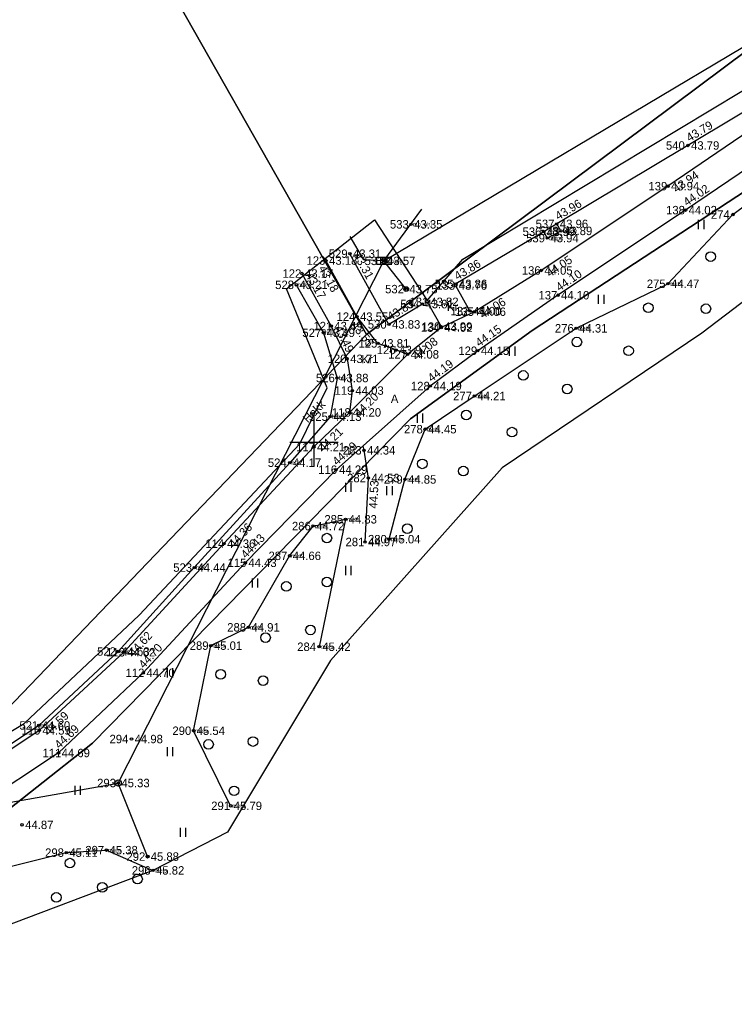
# Model space of a CAD drawing. Extents: x 505800 to 507326, y 6540058 to 6542128.
# Drawn here: x 506275.6 to 506334.8, y 6540254 to 6540335 of the extents above; entities that cross this region are included whole.
import ezdxf

# ---------------------------------------------------------------- set-up
doc = ezdxf.new("R2010")
doc.units = 0
for name, color, linetype in [('AED', 7, 'Continuous'), ('ELRAJATISMP', 7, 'Continuous'), ('HALJASTUS', 7, 'Continuous'), ('KORGUS-EH2000', 7, 'Continuous'), ('MAAMUDEL', 7, 'Continuous'), ('MOOTKORG-EH2000', 7, 'Continuous'), ('MOOTMPUNKT', 7, 'Continuous'), ('MOOTNR', 7, 'Continuous'), ('MOOTPIIR', 7, 'Continuous'), ('MPKAABEL', 7, 'Continuous'), ('MPOHULIIN', 7, 'Continuous'), ('PIIR', 7, 'Continuous'), ('POST', 7, 'Continuous'), ('TEE', 7, 'Continuous'), ('VORK', 7, 'Continuous')]:
    doc.layers.add(name, color=color, linetype=linetype)

msp = doc.modelspace()

# ---------------------------------------------------------------- linework, layer by layer
at = {"layer": 'AED'}
msp.add_line((506319.036, 6540317.461), (506311.755, 6540313.133), dxfattribs=at)
for points in [[(506338.82, 6540329.309), (506330.987, 6540324.61), (506320.117, 6540318.11)], [(506308.981, 6540311.464), (506306.211, 6540309.773), (506302.975, 6540315.637)]]:
    msp.add_lwpolyline(points, dxfattribs=at)
at = {"layer": 'ELRAJATISMP'}
for p, q in [((506305.667, 6540315.342), (506305.667, 6540314.745)), ((506305.938, 6540315.342), (506305.938, 6540314.745))]:
    msp.add_line(p, q, dxfattribs=at)
msp.add_lwpolyline([(506305.205, 6540315.342), (506306.4, 6540315.342), (506306.4, 6540314.745), (506305.205, 6540314.745)], close=True, dxfattribs=at)
at = {"layer": 'HALJASTUS'}
for p, q in [((506331.841, 6540318.44), (506331.841, 6540317.679)), ((506332.296, 6540318.44), (506332.296, 6540317.679)), ((506323.554, 6540312.231), (506323.554, 6540311.47)), ((506324.009, 6540312.231), (506324.009, 6540311.47)), ((506316.187, 6540307.944), (506316.187, 6540307.183)), ((506316.642, 6540307.944), (506316.642, 6540307.183)), ((506308.54, 6540302.376), (506308.54, 6540301.615)), ((506308.995, 6540302.376), (506308.995, 6540301.615)), ((506302.614, 6540296.647), (506302.614, 6540295.886)), ((506303.069, 6540296.647), (506303.069, 6540295.886)), ((506306.017, 6540296.367), (506306.017, 6540295.606)), ((506306.473, 6540296.367), (506306.473, 6540295.606)), ((506302.614, 6540289.757), (506302.614, 6540288.996)), ((506303.069, 6540289.757), (506303.069, 6540288.996)), ((506294.877, 6540288.715), (506294.877, 6540287.954)), ((506295.332, 6540288.715), (506295.332, 6540287.954)), ((506287.831, 6540281.264), (506287.831, 6540280.503)), ((506288.286, 6540281.264), (506288.286, 6540280.503)), ((506287.831, 6540274.734), (506287.831, 6540273.973)), ((506288.286, 6540274.734), (506288.286, 6540273.973)), ((506280.184, 6540271.529), (506280.184, 6540270.768)), ((506280.639, 6540271.529), (506280.639, 6540270.768)), ((506288.912, 6540268.044), (506288.912, 6540267.283)), ((506289.367, 6540268.044), (506289.367, 6540267.283))]:
    msp.add_line(p, q, dxfattribs=at)
for points in [[(506306.227, 6540291.97), (506307.537, 6540296.92), (506309.208, 6540301.088), (506313.28, 6540303.838), (506321.716, 6540309.454), (506329.329, 6540313.144), (506334.711, 6540318.885), (506344.435, 6540326.129), (506351.88, 6540331.712), (506354.071, 6540331.501), (506356.847, 6540327.167), (506360.247, 6540322.568)], [(506298.533, 6540313.056), (506300.788, 6540309.079), (506301.915, 6540305.332), (506301.34, 6540302.125), (506297.996, 6540298.309), (506290.085, 6540289.615), (506283.777, 6540282.658), (506277.199, 6540276.527), (506270.683, 6540272.177), (506261.206, 6540268.283), (506249.615, 6540264.383), (506241.896, 6540261.54), (506240.872, 6540264.129), (506242.157, 6540264.661)], [(506293.096, 6540269.863), (506290.021, 6540276.088), (506291.453, 6540283.145), (506294.563, 6540284.663), (506297.982, 6540290.588), (506299.925, 6540293.056), (506302.613, 6540293.618), (506300.432, 6540283.052)], [(506248.469, 6540250.071), (506251.633, 6540258.04), (506254.539, 6540261.644), (506261.335, 6540263.775), (506263.852, 6540262.439), (506271.144, 6540263.911), (506279.471, 6540265.984), (506282.803, 6540266.189), (506286.653, 6540264.508)]]:
    msp.add_lwpolyline(points, dxfattribs=at)
for centre in [(506332.876, 6540315.4), (506327.711, 6540311.154), (506332.476, 6540311.074), (506321.786, 6540308.309), (506326.07, 6540307.588), (506317.342, 6540305.545), (506320.985, 6540304.424), (506312.617, 6540302.26), (506316.404, 6540300.845), (506308.974, 6540298.214), (506312.377, 6540297.613), (506307.733, 6540292.846), (506301.071, 6540292.058), (506297.708, 6540288.052), (506301.071, 6540288.417), (506299.71, 6540284.447), (506295.987, 6540283.806), (506292.263, 6540280.761), (506295.787, 6540280.24), (506291.262, 6540274.952), (506294.946, 6540275.193), (506293.384, 6540271.106), (506279.775, 6540265.111), (506285.38, 6540263.789), (506282.457, 6540263.108), (506278.654, 6540262.267)]:
    msp.add_circle(centre, 0.4, dxfattribs=at)
at = {"layer": 'KORGUS-EH2000'}
for centre in [(506330.987, 6540324.61), (506329.323, 6540321.237), (506330.786, 6540319.25), (506334.711, 6540318.885), (506308.044, 6540318.072), (506320.117, 6540318.11), (506319.036, 6540317.461), (506320.459, 6540317.528), (506319.332, 6540316.931), (506302.975, 6540315.637), (506300.992, 6540315.071), (506305.802, 6540315.044), (506299, 6540313.993), (506318.831, 6540314.247), (506298.533, 6540313.056), (506311.755, 6540313.133), (506329.329, 6540313.144), (506307.646, 6540312.702), (506311.742, 6540313), (506308.981, 6540311.464), (506309.38, 6540311.646), (506320.213, 6540312.197), (506312.927, 6540310.878), (506313.303, 6540310.828), (506303.553, 6540310.418), (506300.788, 6540309.079), (506301.425, 6540309.637), (506306.211, 6540309.773), (506310.53, 6540309.596), (506310.542, 6540309.512), (506321.716, 6540309.454), (506305.297, 6540308.204), (506306.809, 6540307.659), (506313.574, 6540307.593), (506302.746, 6540306.922), (506307.759, 6540307.29), (506301.915, 6540305.332), (506303.175, 6540304.292), (506309.643, 6540304.666), (506313.28, 6540303.838), (506301.34, 6540302.125), (506302.957, 6540302.479), (506309.208, 6540301.088), (506299.99, 6540299.616), (506304.139, 6540299.338), (506297.996, 6540298.309), (506301.827, 6540297.731), (506304.496, 6540297.04), (506307.537, 6540296.92), (506302.613, 6540293.618), (506299.925, 6540293.056), (506306.227, 6540291.97), (506292.541, 6540291.599), (506304.224, 6540291.74), (506297.982, 6540290.588), (506290.085, 6540289.615), (506294.306, 6540290.01), (506294.563, 6540284.663), (506291.453, 6540283.145), (506300.432, 6540283.052), (506283.777, 6540282.658), (506284.251, 6540282.595), (506285.858, 6540280.887), (506277.199, 6540276.527), (506277.243, 6540276.116), (506290.021, 6540276.088), (506284.88, 6540275.4), (506278.831, 6540274.243), (506283.784, 6540271.755), (506293.096, 6540269.863), (506275.813, 6540268.286), (506282.803, 6540266.189), (506279.471, 6540265.984), (506286.211, 6540265.655), (506286.653, 6540264.508)]:
    msp.add_circle(centre, 0.1, dxfattribs=at)
at = {"layer": 'MOOTMPUNKT'}
for centre in [(506330.987, 6540324.61), (506329.323, 6540321.237), (506330.786, 6540319.25), (506334.711, 6540318.885), (506308.044, 6540318.072), (506320.117, 6540318.11), (506319.036, 6540317.461), (506320.459, 6540317.528), (506319.332, 6540316.931), (506302.975, 6540315.637), (506300.992, 6540315.071), (506305.802, 6540315.044), (506299, 6540313.993), (506318.831, 6540314.247), (506298.533, 6540313.056), (506311.755, 6540313.133), (506329.329, 6540313.144), (506307.646, 6540312.702), (506311.742, 6540313), (506308.981, 6540311.464), (506309.38, 6540311.646), (506320.213, 6540312.197), (506312.927, 6540310.878), (506313.303, 6540310.828), (506303.553, 6540310.418), (506300.788, 6540309.079), (506301.425, 6540309.637), (506306.211, 6540309.773), (506310.53, 6540309.596), (506310.542, 6540309.512), (506321.716, 6540309.454), (506305.297, 6540308.204), (506306.809, 6540307.659), (506313.574, 6540307.593), (506302.746, 6540306.922), (506307.759, 6540307.29), (506301.915, 6540305.332), (506303.175, 6540304.292), (506309.643, 6540304.666), (506313.28, 6540303.838), (506301.34, 6540302.125), (506302.957, 6540302.479), (506309.208, 6540301.088), (506299.99, 6540299.616), (506304.139, 6540299.338), (506297.996, 6540298.309), (506301.827, 6540297.731), (506304.496, 6540297.04), (506307.537, 6540296.92), (506302.613, 6540293.618), (506299.925, 6540293.056), (506306.227, 6540291.97), (506292.541, 6540291.599), (506304.224, 6540291.74), (506297.982, 6540290.588), (506290.085, 6540289.615), (506294.306, 6540290.01), (506294.563, 6540284.663), (506291.453, 6540283.145), (506300.432, 6540283.052), (506283.777, 6540282.658), (506284.251, 6540282.595), (506285.858, 6540280.887), (506277.199, 6540276.527), (506277.243, 6540276.116), (506290.021, 6540276.088), (506284.88, 6540275.4), (506278.831, 6540274.243), (506283.784, 6540271.755), (506293.096, 6540269.863), (506275.813, 6540268.286), (506282.803, 6540266.189), (506279.471, 6540265.984), (506286.211, 6540265.655), (506286.653, 6540264.508)]:
    msp.add_circle(centre, 0.1, dxfattribs=at)
at = {"layer": 'MOOTPIIR'}
for points in [[(506240.253, 6540270.959), (506245.955, 6540263.864), (506266.133, 6540270.794), (506275.983, 6540276.683), (506285.511, 6540285.657), (506298.843, 6540299.878), (506301.086, 6540304.525), (506297.722, 6540312.738), (506305.023, 6540318.445), (506309.38, 6540311.746), (506312.325, 6540315.185), (506338.029, 6540330.648), (506336.908, 6540340.183), (506347.357, 6540347.554), (506370.89, 6540361.705), (506382.389, 6540366.462), (506390.076, 6540368.866), (506400.572, 6540374.13), (506410.565, 6540381.71), (506441.143, 6540393.151), (506453.59, 6540403.335), (506461.402, 6540393.473), (506495.448, 6540402.285)], [(506495.183, 6540386.603), (506455.807, 6540378.751), (506413.936, 6540356.957), (506411.426, 6540354.112), (506402.307, 6540351.523), (506391.999, 6540341.498), (506380.901, 6540334.942), (506360.247, 6540322.568), (506353.013, 6540324.95), (506332.133, 6540309.036), (506315.598, 6540297.889), (506301.375, 6540281.904), (506292.827, 6540267.673), (506286.653, 6540264.508), (506248.469, 6540250.071)]]:
    msp.add_lwpolyline(points, dxfattribs=at)
at = {"layer": 'MPKAABEL'}
msp.add_lwpolyline([(506305.802, 6540315.044), (506304.129, 6540315.129), (506302.991, 6540317.073)], dxfattribs=at)
at = {"layer": 'MPOHULIIN'}
for q in [(506338.064, 6540334.279), (506308.946, 6540319.316)]:
    msp.add_line((506305.802, 6540315.044), q, dxfattribs=at)
msp.add_lwpolyline([(506112.189, 6540233.927), (506153.828, 6540249.522), (506196.936, 6540256.778), (506240.207, 6540264.027), (506283.784, 6540271.755), (506305.802, 6540315.044)], dxfattribs=at)
at = {"layer": 'PIIR'}
for points in [[(506215.95, 6540254.34), (506268.55, 6540273.9), (506274.54, 6540277.85), (506304.35, 6540308.95), (506340.34, 6540335.82), (506458.7, 6540391.28), (506563.96, 6540420.02)], [(506497.85, 6540391.32), (506462.8, 6540384.69), (506453.27, 6540382.76), (506413.82, 6540364.84), (506374.55, 6540342.6), (506353.59, 6540332.53), (506318.07, 6540309.28), (506308, 6540301.95), (506281.65, 6540275.05), (506272.39, 6540267.75), (506224.13, 6540249.92)], [(506224.13, 6540249.92), (506272.39, 6540267.75), (506281.65, 6540275.05), (506308, 6540301.95), (506318.07, 6540309.28), (506353.59, 6540332.53), (506374.55, 6540342.6), (506413.82, 6540364.84), (506453.27, 6540382.76), (506462.8, 6540384.69), (506495.14, 6540337.45), (506342.85, 6540237.27), (506260.72, 6540195.9), (506215.68, 6540179.69)]]:
    msp.add_lwpolyline(points, dxfattribs=at)
for points in [[(506281.36, 6540349.61), (506321.08, 6540373.36), (506324.04, 6540375.18), (506326.14, 6540370.11), (506340.34, 6540335.82), (506304.35, 6540308.95), (506282.62, 6540347.28)], [(506190.15, 6540321.81), (506202.45, 6540325.81), (506206.43, 6540327.67), (506257.9, 6540343.01), (506275.56, 6540347.96), (506281.36, 6540349.61), (506282.62, 6540347.28), (506304.35, 6540308.95), (506274.54, 6540277.85), (506268.55, 6540273.9), (506215.95, 6540254.34)]]:
    msp.add_lwpolyline(points, close=True, dxfattribs=at)
at = {"layer": 'POST'}
for points in [[(506307.646, 6540312.702), (506305.802, 6540315.044)], [(506286.211, 6540265.655), (506283.784, 6540271.755)]]:
    msp.add_lwpolyline(points, dxfattribs=at)
for centre, radius in [((506305.802, 6540315.044), 0.25), ((506307.646, 6540312.702), 0.2), ((506283.784, 6540271.755), 0.25), ((506286.211, 6540265.655), 0.125), ((506286.211, 6540265.655), 0.105), ((506286.211, 6540265.655), 0.0851), ((506286.211, 6540265.655), 0.0651), ((506286.211, 6540265.655), 0.0451), ((506286.211, 6540265.655), 0.0251), ((506286.211, 6540265.655), 0.00511)]:
    msp.add_circle(centre, radius, dxfattribs=at)
at = {"layer": 'TEE'}
for points in [[(506340.898, 6540329.111), (506329.323, 6540321.237), (506318.831, 6540314.247), (506313.303, 6540310.828), (506310.542, 6540309.512), (506307.759, 6540307.29), (506302.957, 6540302.479), (506299.99, 6540299.616), (506292.541, 6540291.599), (506284.251, 6540282.595), (506277.243, 6540276.116), (506270.928, 6540271.917), (506261.747, 6540268.058), (506250.031, 6540264.042), (506237.432, 6540259.066)], [(506342.338, 6540327.065), (506330.786, 6540319.25), (506320.213, 6540312.197), (506313.574, 6540307.593), (506309.643, 6540304.666), (506301.827, 6540297.731), (506294.306, 6540290.01), (506285.858, 6540280.887), (506278.831, 6540274.243), (506272.138, 6540269.835), (506262.639, 6540265.724), (506250.904, 6540261.782), (506238.366, 6540256.809)], [(506319.036, 6540317.461), (506319.332, 6540316.931), (506320.459, 6540317.528), (506320.117, 6540318.11)], [(506320.117, 6540318.11), (506319.036, 6540317.461)], [(506307.759, 6540307.29), (506306.809, 6540307.659), (506305.297, 6540308.204), (506303.553, 6540310.418), (506300.992, 6540315.071)], [(506299, 6540313.993), (506301.425, 6540309.637), (506302.746, 6540306.922), (506303.175, 6540304.292), (506302.957, 6540302.479)], [(506311.742, 6540313), (506312.927, 6540310.878), (506313.303, 6540310.828)], [(506309.38, 6540311.646), (506310.53, 6540309.596), (506310.542, 6540309.512)], [(506304.059, 6540299.711), (506304.139, 6540299.338), (506304.496, 6540297.04), (506304.224, 6540291.74)]]:
    msp.add_lwpolyline(points, dxfattribs=at)
at = {"layer": 'VORK'}
for p, q in [((506300, 6540302), (506300, 6540298)), ((506298, 6540300), (506302, 6540300))]:
    msp.add_line(p, q, dxfattribs=at)

# ---------------------------------------------------------------- texts
at = {"layer": 'HALJASTUS'}
msp.add_text('Hekk', height=0.7, rotation=44.60512, dxfattribs=at).set_placement((506299.489, 6540301.567))
at = {"layer": 'KORGUS-EH2000'}
for s, rotation, p in [(' 43.79', 30.95913, (506330.897, 6540324.76)), (' 43.94', 34.22893, (506329.815, 6540320.513)), (' 44.02', 34.07894, (506330.688, 6540319.395)), (' 43.96', 30.87686, (506320.027, 6540318.26)), (' 43.31', 298.89575, (506303.128, 6540315.722)), (' 43.86', 30.72989, (506311.666, 6540313.283)), (' 44.05', 33.66914, (506319.316, 6540313.519)), (' 43.18', 298.83381, (506300.226, 6540314.649)), (' 44.10', 33.70607, (506320.116, 6540312.343)), (' 43.17', 299.10539, (506299.153, 6540314.078)), (' 43.83', 31.41668, (506306.12, 6540309.922)), (' 44.06', 31.74003, (506313.763, 6540310.084)), (' 43.49', 295.93607, (506301.583, 6540309.713)), (' 43.55', 308.20678, (506302.866, 6540309.877)), (' 44.15', 34.73803, (506313.474, 6540307.737)), (' 44.08', 38.60605, (506308.305, 6540306.606)), (' 44.19', 36.67092, (506309.538, 6540304.807)), (' 44.20', 45.05186, (506303.576, 6540301.861)), (' 44.21', 43.98381, (506300.598, 6540298.986)), (' 44.29', 41.58341, (506301.71, 6540297.862)), (' 44.53', 87.0633, (506305.228, 6540294.23)), (' 44.36', 47.09986, (506293.181, 6540291.003)), (' 44.43', 45.7533, (506294.181, 6540290.132)), (' 44.62', 47.36658, (506284.895, 6540282.002)), (' 44.70', 47.19804, (506285.73, 6540281.006)), (' 44.59', 42.75004, (506277.837, 6540275.474)), (' 44.69', 43.39731, (506278.711, 6540274.37))]:
    msp.add_text(s, height=0.7, rotation=rotation, dxfattribs=at).set_placement(p)
for s, p in [(' 44.47', (506329.329, 6540312.794)), (' 44.31', (506321.716, 6540309.104)), (' 44.21', (506313.28, 6540303.488)), (' 44.45', (506309.208, 6540300.738)), (' 44.85', (506307.537, 6540296.57)), (' 44.72', (506299.925, 6540292.706)), (' 45.04', (506306.227, 6540291.62)), (' 44.66', (506297.982, 6540290.238)), (' 44.91', (506294.563, 6540284.312)), (' 45.01', (506291.453, 6540282.795)), (' 45.42', (506300.432, 6540282.701)), (' 45.54', (506290.021, 6540275.738)), (' 44.98', (506284.88, 6540275.05)), (' 45.33', (506283.784, 6540271.405)), (' 45.79', (506293.096, 6540269.513)), (' 44.87', (506275.813, 6540267.936)), (' 45.11', (506279.471, 6540265.634)), (' 45.82', (506286.653, 6540264.158))]:
    msp.add_text(s, height=0.7, dxfattribs=at).set_placement(p)
at = {"layer": 'MAAMUDEL'}
for s, p in [(' mp_ohl', (506308.044, 6540317.897)), (' beton', (506320.459, 6540317.353)), (' beton', (506319.332, 6540316.756)), (' elkapp', (506305.802, 6540314.869)), (' hek', (506298.533, 6540312.881)), (' mets', (506329.329, 6540312.969)), (' hek', (506300.788, 6540308.904)), (' mets', (506321.716, 6540309.279)), (' hek', (506301.915, 6540305.157)), (' mets', (506313.28, 6540303.663)), (' hek', (506301.34, 6540301.95)), (' mets', (506309.208, 6540300.913)), (' hek', (506297.996, 6540298.134)), (' mets', (506307.537, 6540296.745)), (' mets', (506302.613, 6540293.443)), (' mets', (506299.925, 6540292.881)), (' mets', (506306.227, 6540291.795)), (' mets', (506297.982, 6540290.413)), (' hek', (506290.085, 6540289.44)), (' mets', (506294.563, 6540284.487)), (' mets', (506291.453, 6540282.97)), (' mets', (506300.432, 6540282.877)), (' hek', (506283.777, 6540282.483)), (' hek', (506277.199, 6540276.352)), (' mets', (506290.021, 6540275.913)), (' mets', (506293.096, 6540269.688)), (' mets', (506279.471, 6540265.809)), (' mets', (506282.803, 6540266.014)), (' mets', (506286.653, 6540264.333))]:
    msp.add_text(s, height=0.35, dxfattribs=at).set_placement(p)
at = {"layer": 'MOOTKORG-EH2000'}
for s, p in [(' 43.79', (506330.987, 6540324.26)), (' 43.94', (506329.323, 6540320.887)), (' 44.02', (506330.786, 6540318.9)), (' 43.35', (506308.044, 6540317.722)), (' 43.96', (506320.117, 6540317.76)), (' 43.99', (506319.036, 6540317.111)), (' 43.94', (506319.332, 6540316.581)), (' 43.89', (506320.459, 6540317.178)), (' 43.31', (506302.975, 6540315.287)), (' 43.18', (506300.992, 6540314.721)), (' 43.57', (506305.802, 6540314.694)), (' 43.17', (506299, 6540313.643)), (' 44.05', (506318.831, 6540313.897)), (' 43.21', (506298.533, 6540312.706)), (' 43.76', (506311.742, 6540312.65)), (' 43.86', (506311.755, 6540312.783)), (' 44.47', (506329.329, 6540312.794)), (' 43.75', (506307.646, 6540312.352)), (' 44.10', (506320.213, 6540311.847)), (' 43.81', (506308.981, 6540311.114)), (' 43.82', (506309.38, 6540311.296)), (' 43.55', (506303.553, 6540310.068)), (' 44.00', (506312.927, 6540310.528)), (' 44.06', (506313.303, 6540310.478)), (' 43.49', (506301.425, 6540309.287)), (' 43.83', (506306.211, 6540309.423)), (' 43.99', (506310.53, 6540309.246)), (' 43.49', (506300.788, 6540308.729)), (' 44.02', (506310.542, 6540309.162)), (' 44.31', (506321.716, 6540309.104)), (' 43.81', (506305.297, 6540307.854)), (' 43.97', (506306.809, 6540307.309)), (' 44.08', (506307.759, 6540306.94)), (' 44.15', (506313.574, 6540307.243)), (' 43.71', (506302.746, 6540306.572)), (' 43.88', (506301.915, 6540304.982)), (' 44.03', (506303.175, 6540303.941)), (' 44.19', (506309.643, 6540304.316)), (' 44.21', (506313.28, 6540303.488)), (' 44.20', (506302.957, 6540302.129)), (' 44.13', (506301.34, 6540301.775)), (' 44.45', (506309.208, 6540300.738)), (' 44.21', (506299.99, 6540299.266)), (' 44.34', (506304.139, 6540298.988)), (' 44.17', (506297.996, 6540297.959)), (' 44.29', (506301.827, 6540297.381)), (' 44.53', (506304.496, 6540296.69)), (' 44.85', (506307.537, 6540296.57)), (' 44.83', (506302.613, 6540293.268)), (' 44.72', (506299.925, 6540292.706)), (' 44.97', (506304.224, 6540291.39)), (' 45.04', (506306.227, 6540291.62)), (' 44.36', (506292.541, 6540291.249)), (' 44.66', (506297.982, 6540290.238)), (' 44.44', (506290.085, 6540289.265)), (' 44.43', (506294.306, 6540289.66)), (' 44.91', (506294.563, 6540284.312)), (' 45.01', (506291.453, 6540282.795)), (' 45.42', (506300.432, 6540282.701)), (' 44.63', (506283.777, 6540282.308)), (' 44.62', (506284.251, 6540282.245)), (' 44.70', (506285.858, 6540280.537)), (' 44.60', (506277.199, 6540276.177)), (' 44.59', (506277.243, 6540275.766)), (' 45.54', (506290.021, 6540275.738)), (' 44.98', (506284.88, 6540275.05)), (' 44.69', (506278.831, 6540273.893)), (' 45.33', (506283.784, 6540271.405)), (' 45.79', (506293.096, 6540269.513)), (' 44.87', (506275.813, 6540267.936)), (' 45.11', (506279.471, 6540265.634)), (' 45.38', (506282.803, 6540265.839)), (' 45.88', (506286.211, 6540265.305)), (' 45.82', (506286.653, 6540264.158))]:
    msp.add_text(s, height=0.7, dxfattribs=at).set_placement(p)
at = {"layer": 'MOOTNR'}
for s, p in [('540 ', (506329.167, 6540324.26)), ('139 ', (506327.713, 6540320.887)), ('138 ', (506329.176, 6540318.9)), ('274 ', (506332.891, 6540318.535)), ('533 ', (506306.294, 6540317.722)), ('537 ', (506318.367, 6540317.76)), ('536 ', (506317.286, 6540317.111)), ('539 ', (506317.582, 6540316.581)), ('538 ', (506318.709, 6540317.178)), ('529 ', (506301.225, 6540315.287)), ('123 ', (506299.382, 6540314.721)), ('531 ', (506304.193, 6540314.694)), ('122 ', (506297.39, 6540313.643)), ('136 ', (506317.221, 6540313.897)), ('528 ', (506296.783, 6540312.706)), ('535 ', (506310.005, 6540312.783)), ('133 ', (506310.132, 6540312.65)), ('275 ', (506327.579, 6540312.794)), ('532 ', (506305.896, 6540312.352)), ('137 ', (506318.603, 6540311.847)), ('534 ', (506307.161, 6540311.114)), ('131 ', (506307.91, 6540311.296)), ('124 ', (506301.873, 6540310.068)), ('132 ', (506311.317, 6540310.528)), ('135 ', (506311.693, 6540310.478)), ('121 ', (506299.955, 6540309.287)), ('530 ', (506304.461, 6540309.423)), ('130 ', (506308.92, 6540309.246)), ('527 ', (506299.038, 6540308.729)), ('134 ', (506308.862, 6540309.162)), ('276 ', (506319.966, 6540309.104)), ('125 ', (506303.687, 6540307.854)), ('126 ', (506305.199, 6540307.309)), ('127 ', (506306.149, 6540306.94)), ('129 ', (506311.964, 6540307.243)), ('120 ', (506301.136, 6540306.572)), ('526 ', (506300.165, 6540304.982)), ('119 ', (506301.705, 6540303.941)), ('128 ', (506308.033, 6540304.316)), ('277 ', (506311.531, 6540303.488)), ('118 ', (506301.487, 6540302.129)), ('525 ', (506299.59, 6540301.775)), ('278 ', (506307.458, 6540300.738)), ('117 ', (506298.52, 6540299.266)), ('283 ', (506302.389, 6540298.988)), ('524 ', (506296.176, 6540297.959)), ('116 ', (506300.357, 6540297.381)), ('282 ', (506302.746, 6540296.69)), ('279 ', (506305.787, 6540296.57)), ('285 ', (506300.863, 6540293.268)), ('286 ', (506298.175, 6540292.706)), ('281 ', (506302.614, 6540291.39)), ('280 ', (506304.477, 6540291.62)), ('114 ', (506291.001, 6540291.249)), ('287 ', (506296.232, 6540290.238)), ('523 ', (506288.336, 6540289.265)), ('115 ', (506292.836, 6540289.66)), ('288 ', (506292.813, 6540284.312)), ('289 ', (506289.703, 6540282.795)), ('284 ', (506298.612, 6540282.701)), ('522 ', (506282.027, 6540282.308)), ('113 ', (506282.781, 6540282.245)), ('112 ', (506284.388, 6540280.537)), ('521 ', (506275.589, 6540276.177)), ('110 ', (506275.773, 6540275.766)), ('290 ', (506288.271, 6540275.738)), ('294 ', (506283.06, 6540275.05)), ('111 ', (506277.501, 6540273.893)), ('293 ', (506282.034, 6540271.405)), ('291 ', (506291.486, 6540269.513)), ('298 ', (506277.721, 6540265.634)), ('297 ', (506281.053, 6540265.839)), ('292 ', (506284.461, 6540265.305)), ('296 ', (506284.903, 6540264.158))]:
    msp.add_text(s, height=0.7, dxfattribs=at).set_placement(p)
at = {"layer": 'TEE'}
msp.add_text('Betoon', height=0.175, rotation=27.6963, dxfattribs=at).set_placement((506319.463, 6540317.281))
for s, p in [('Kr', (506311.015, 6540310.886)), ('Kr', (506303.934, 6540306.536)), ('A', (506306.37, 6540303.264))]:
    msp.add_text(s, height=0.7, dxfattribs=at).set_placement(p)

doc.saveas('drawing.dxf')
